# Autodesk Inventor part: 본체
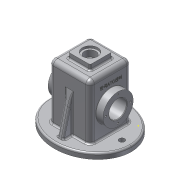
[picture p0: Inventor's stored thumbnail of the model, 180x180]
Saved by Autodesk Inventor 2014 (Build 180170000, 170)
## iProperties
Created: 2017-07
Part Number: 본체
Material: 알루미늄 6061
Document SubType Name: Modeling
Designer: user
Density: 2.71 g/cm^3
Appearance: 알루미늄 - 평지
Mass: 957.949 g
Surface Area: 976.832 cm^2
Volume: 353.487 cm^3
Author: user
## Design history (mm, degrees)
sketch "스케치1"
  geometry: L1 (0, 0)-(-75, 0); L2 (-75, 0)-(-75, 75); L3 (-75, 75)-(0, 75); L4 (0, 75)-(0, 0)
  constraints: 8 end point, 2 parallel, 1 horizontal, 1 perpendicular
  dimensions: "d0" = 75 distance of L2.end L3.end; "d1" = 75 distance of L1.end L2.end
extrude "돌출1" new body sketch "스케치1" distance "d2" = 100; taper "d3" = 0 deg
sketch "스케치2"
  geometry: L1 (0, 0)-(75, 0) reference; L2 (37.5, 37.5)-(112.5, 37.5); L3 (37.5, 37.5)-(37.5, 102.5); 1 other entity
  constraints: 4 end point, 2 horizontal, 1 vertical, 4 other
  dimensions: "d4" = 65 distance of L2.start L3.end; "d5" = 75 distance of L2.start L2.end
extrude "돌출2" join sketch "스케치2" distance "d6" = 10; taper "d7" = 0 deg
node "작업 평면1"
sketch "스케치4"
  geometry: L1 (17.5, -17.5)-(57.5, -17.5); L2 (57.5, -17.5)-(57.5, -57.5); L3 (57.5, -57.5)-(17.5, -57.5); L4 (17.5, -57.5)-(17.5, -17.5); L5 (17.5, -17.5)-(57.5, -57.5); L6 (57.5, -17.5)-(17.5, -57.5); 1 further point
  constraints: 12 end point, 2 midpoint, 2 parallel, 1 horizontal, 1 perpendicular
  dimensions: "d14" = 40 distance of L2.end L3.end; "d15" = 40 distance of L1.end L2.end
extrude "돌출4" join sketch "스케치4" distance "d16" = 10; taper "d17" = 0 deg
node "작업 평면2"
sketch "스케치5"
  geometry: 1 further point
sketch "스케치6"
  geometry: L1 (-27.5, -110)-(102.5, -110) reference; L2 (75, -100)-(75, 0) reference; C1 r 27.5 at (38, -55)
  constraints: 1 centre point
  dimensions: "d19" = 55 diameter of C1; "d20" = 55 distance from line of L1 C1.centre; "d21" = 37 distance from line of L2 C1.centre
extrude "돌출5" join sketch "스케치6" distance "d22" = 100; taper "d23" = 0 deg
sketch "스케치7"
  geometry: C1 r 27.5 at (0, 0) reference; C2 r 16 at (0, 0); 1 further point
  constraints: 1 centre point, 1 coincident
  dimensions: "d24" = 32 diameter of C2
extrude "돌출6" cut sketch "스케치7" stored distance "d25" = 100; taper "d26" = 0 deg
node "작업 평면3"
sketch "스케치8"
  geometry: L1 (0, 75)-(100, 75) reference; L2 (0, 0)-(100, 0) reference; L3 (0, -27.5)-(0, 102.5) reference; L4 (70.189, 75)-(0, 92.5); L5 (0, 92.5)-(0, 102.5); L6 (0, 102.5)-(35.183, 102.5)
  constraints: 6 end point, 2 point on line, 1 collinear, 1 perpendicular
  dimensions: "d27" = 10 distance of L4.end L3.end; "d28" = 14 deg angle of L4 L6
feature "리브1" sketch "스케치8" dims "d29" = 1, "d30" = 10, "d31" = 0, "d32" = 0, "d33" = 1, "d34" = 1
node "작업 평면4"
sketch "스케치9"
  geometry: C1 r 14 at (37.5, -37.5); 1 further point
  constraints: 1 centre point
  dimensions: "d35" = 28 diameter of C1
extrude "돌출7" cut sketch "스케치9" distance "d36" = 4; taper "d37" = 0 deg
sketch "스케치10"
  geometry: C1 r 14 at (0, 0) reference; C2 r 10.5 at (0, 0); 1 further point
  constraints: 1 centre point, 1 coincident
  dimensions: "d38" = 21 diameter of C2
extrude "돌출8" cut sketch "스케치10" stored distance "d39" = 4; taper "d40" = 0 deg
sketch "스케치11"
  geometry: C1 r 5 at (95.5, -37.5); C2 r 5 at (-20.5, -37.5); 1 further point; 1 other entity
  constraints: 2 centre point, 1 horizontal alignment, 1 other
  dimensions: "d41" = 10 diameter of C1; "d42" = 10 diameter of C2; "d43" = 58 distance of point (37.5, -37.5) C2.centre; "d44" = 58 distance of C1.centre point (37.5, -37.5)
extrude "돌출9" cut sketch "스케치11" stored distance "d45" = 4; taper "d46" = 0 deg
node "작업 평면5"
fillet "모깎기1" dims "d55" = 8
fillet "모깎기2" dims "d56" = 8
fillet "모깎기3" dims "d57" = 3
fillet "모깎기4" dims "d58" = 3
node "작업 평면6"
sketch "스케치13"
  geometry: L1 (-32.5, -67.189)-(-32.5, 21.811) reference; L2 (-24.5, 29.811)-(34.5, 29.811) reference; L3 (42.5, 21.811)-(42.5, -67.189) reference; L4 (34.5, 24.811)-(-24.5, 24.811); L5 (-70, -80.189)-(80, -80.189) reference; L6 (55.5, 2.311)-(42.5, 2.311) reference; L7 (55.5, -52.689)-(42.5, -52.689) reference; L8 (42.5, -52.689)-(24.205, -52.689); L9 (37.5, -52.689)-(30.5, -45.689); L10 (42.5, 2.311)-(26.221, 2.311); L11 (37.5, 2.311)-(30.5, -4.689); L12 (30.5, -4.689)-(30.5, -45.689); L13 (37.5, -80.189)-(37.5, -52.689); L14 (37.5, 2.311)-(37.5, 21.811); L15 (5, 24.811)-(5, -80.189); L16 (-27.5, 2.311)-(-20.5, -4.689); L17 (-20.5, -4.689)-(-20.5, -45.689); L18 (-27.5, -52.689)-(-20.5, -45.689); L19 (-27.5, -80.189)-(37.5, -80.189); L20 (-27.5, 21.811)-(-27.5, 2.311); L21 (-27.5, -52.689)-(-27.5, -80.189); A1 r 8 centre (-24.5, 21.811) between (-24.5, 29.811) and (-32.5, 21.811) reference; A2 r 8 centre (34.5, 21.811) between (42.5, 21.811) and (34.5, 29.811) reference; A3 r 3 centre (34.5, 21.811) between (37.5, 21.811) and (34.5, 24.811); A4 r 3 centre (-24.5, 21.811) between (-24.5, 24.811) and (-27.5, 21.811); 1 further point
  constraints: 30 end point, 4 point on circle, 4 point on line, 4 symmetric about line, 3 perpendicular, 2 centre point, 2 midpoint, 1 collinear, 1 parallel, 2 other
  dimensions: "d61" = 7 horizontal distance of L9.start L9.end; "d62" = 7 horizontal distance of L11.start L11.end
extrude "돌출11" cut sketch "스케치13" stored distance "d63" = 64; taper "d64" = 0 deg
fillet "모깎기5" dims "d65" = 0.5
node "작업 평면7"
fillet "모깎기7" dims "d67" = 3
chamfer "모따기1" distance "d68" = 1; stored, may be unused: second distance "d69" = 2, angle "d70" = 45 deg
sketch "스케치14" dims "d74" = 45
  geometry: L1 (0, 0)-(0, 22.5); C1 r 17 at (0, 0) reference; 2 further points
  constraints: 2 coincident, 2 end point, 1 vertical, 1 vertical alignment, 2 other
hole "구멍1" sketch "스케치14" at (0, 22.5) diameter "d75" = 3.242; stored, may be unused: countersink angle "d79" = 90 deg, drill point angle "d81" = 118 deg; dims "d76" = 8, "d77" = 4, "d78" = 2, "d80" = 10
sketch "스케치15" dims "d85" = 45
  geometry: L1 (0, 0)-(0, 22.5); C1 r 17 at (0, 0) reference; 2 further points
  constraints: 2 coincident, 2 end point, 1 vertical, 1 vertical alignment, 2 other
hole "구멍2" sketch "스케치15" at (0, 22.5) diameter "d86" = 3.242; stored, may be unused: countersink angle "d90" = 90 deg, drill point angle "d92" = 118 deg; dims "d87" = 8, "d88" = 4, "d89" = 2, "d91" = 10
fillet "모깎기8" dims "d96" = 3
sketch "스케치16"
  geometry: L1 (12.5, 18)-(46.5, 18) reference; L2 (67, -89)-(67, 0) reference; 2 further points
  constraints: 1 other
  dimensions: "d97" = 30 distance from line of L1 point (30, -12); "d98" = 37 distance from line of L2 point (30, -12)
feature "엠보싱1" sketch "스케치16" dims "d14" = 40, "d15" = 40, "d99" = 0.5, "d100" = 0
fillet "모깎기9" dims "d101" = 0.5
node "솔리드1"
mirror "대칭1"
pattern_circular "원형 패턴1" dims angle "d83" = 360 deg
pattern_circular "원형 패턴2" dims angle "d94" = 360 deg
other parameters: "d8" = 13, "d18" = 13, "d50" = 135 deg, "d59" = 5, "d60" = 135 deg
